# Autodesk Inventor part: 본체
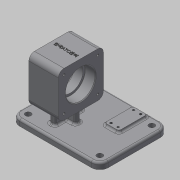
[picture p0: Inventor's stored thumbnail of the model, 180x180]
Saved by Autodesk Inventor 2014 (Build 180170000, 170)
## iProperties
Created: 2019-09
Part Number: 본체
Material: 일반
Document SubType Name: Modeling
Designer: mduedu
Density: 1 g/cm^3
Appearance: 기본값
Author: mduedu
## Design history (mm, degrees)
sketch "스케치1"
  geometry: L1 (42, -62)-(-84, -62); L2 (-84, -62)-(-84, 36); L3 (-84, 36)-(42, 36); L4 (42, 36)-(42, -62); 1 further point
  constraints: 8 end point, 2 parallel, 1 horizontal, 1 perpendicular
  dimensions: "d0" = 36 distance from line of L3 point (0, 0); "d1" = 98 distance of L1.end L2.end; "d2" = 42 distance from line of L4 point (0, 0); "d3" = 126 distance of L2.end L3.end
extrude "돌출1" new body sketch "스케치1" distance "d4" = 9; taper "d5" = 0 deg
sketch "스케치2"
  geometry: L1 (0, -62)-(0, 36) reference; L2 (27, -32)-(91, -32); L3 (91, -32)-(91, 32); L4 (91, 32)-(27, 32); L5 (27, 32)-(27, -32); L6 (27, -32)-(91, 32); L7 (91, -32)-(27, 32); 3 further points
  constraints: 12 end point, 3 midpoint, 2 parallel, 1 horizontal, 1 horizontal alignment, 1 perpendicular
  dimensions: "d87" = 64 distance of L4.end L3.end; "d88" = 64 distance of L3.end L2.end; "d89" = 59 distance from line of point (59, 0) L1
extrude "돌출2" join sketch "스케치2" stored distance "d8" = 42; taper "d9" = 0 deg
sketch "스케치3"
  geometry: L1 (-17, 4)-(17, 4); L2 (17, 4)-(17, -4); L3 (17, -4)-(-17, -4); L4 (-17, -4)-(-17, 4); L5 (-4, 20)-(4, 20); L6 (4, 20)-(4, -20); L7 (4, -20)-(-4, -20); L8 (-4, -20)-(-4, 20); 5 further points
  constraints: 16 end point, 4 midpoint, 4 parallel, 2 horizontal, 2 horizontal alignment, 2 perpendicular, 2 vertical alignment
  dimensions: "d10" = 8 distance of L5.start L5.end; "d12" = 8 distance of L1.end L2.end; "d13" = 34 distance of L2.end L3.end; "d14" = 40 distance of L5.end L6.end
extrude "돌출3" join sketch "스케치3" stored distance "d15" = 42; taper "d16" = 0 deg
sketch "스케치4"
  geometry: L1 (-32, 91)-(-32, 27) reference; L2 (32, 91)-(-32, 91) reference; L3 (32, 27)-(32, 91) reference; L4 (-32, 27)-(32, 27) reference; C1 r 21 at (0, 59); 3 further points
  constraints: 2 midpoint, 1 centre point, 1 horizontal alignment, 1 vertical alignment
  dimensions: "d17" = 42 diameter of C1
extrude "돌출4" cut sketch "스케치4" distance "d18" = 15; taper "d19" = 0 deg
hole "구멍1" diameter "d22" = 36; stored, may be unused: countersink angle "d26" = 90 deg, drill point angle "d28" = 118 deg; dims "d20" = 10, "d21" = 10, "d23" = 6, "d24" = 4, "d25" = 2, "d27" = 8
fillet "모깎기1" dims "d29" = 0.3
chamfer "모따기1" distance "d30" = 1; stored, may be unused: second distance "d31" = 2, angle "d32" = 45 deg
fillet "모깎기9" dims "d90" = 8
sketch "스케치11"
  geometry: L1 (-24, 27)-(24, 27) reference; L2 (32, 35)-(32, 83) reference; L3 (24, 91)-(-24, 91) reference; L4 (-32, 83)-(-32, 35) reference; C1 r 22 at (0, 59) reference; A1 r 8 centre (-24, 35) between (-32, 35) and (-24, 27) reference; A2 r 8 centre (24, 35) between (24, 27) and (32, 35) reference; A3 r 8 centre (24, 83) between (32, 83) and (24, 91) reference; A4 r 8 centre (-24, 83) between (-24, 91) and (-32, 83) reference; 5 further points
  constraints: 4 coincident
hole "구멍6" sketch "스케치11" at (-24, 83), (24, 83), (24, 35), (-24, 35) diameter "d91" = 3.242; stored, may be unused: countersink angle "d95" = 90 deg, drill point angle "d97" = 118 deg; dims "d92" = 8, "d93" = 4, "d94" = 2, "d96" = 10
fillet "모깎기2" dims "d44" = 12
sketch "스케치6"
  geometry: L1 (-42, 50)-(-42, -24) reference; L2 (-30, -36)-(72, -36) reference; L3 (84, -24)-(84, 50) reference; L4 (72, 62)-(-30, 62) reference; L5 (17, 4)-(17, -4) reference; L6 (17, -4)-(4, -4) reference; L7 (4, -4)-(4, -20) reference; L8 (4, -20)-(-4, -20) reference; L9 (-4, -20)-(-4, -4) reference; L10 (-4, -4)-(-17, -4) reference; L11 (-17, -4)-(-17, 4) reference; L12 (-17, 4)-(-4, 4) reference; L13 (-4, 4)-(-4, 20) reference; L14 (-4, 20)-(4, 20) reference; L15 (4, 20)-(4, 4) reference; L16 (4, 4)-(17, 4) reference; A1 r 12 centre (-30, 50) between (-30, 62) and (-42, 50) reference; A2 r 12 centre (-30, -24) between (-42, -24) and (-30, -36) reference; A3 r 12 centre (72, -24) between (72, -36) and (84, -24) reference; A4 r 12 centre (72, 50) between (84, 50) and (72, 62) reference; 5 further points
  constraints: 4 coincident
hole "구멍3" sketch "스케치6" at (-30, 50), (72, 50), (72, -24), (-30, -24) diameter "d45" = 8; stored, may be unused: countersink angle "d49" = 90 deg, drill point angle "d51" = 118 deg; dims "d46" = 8, "d47" = 4, "d48" = 2, "d50" = 10
sketch "스케치7"
  geometry: L1 (38, 57)-(58, 57); L2 (58, 57)-(58, 17); L3 (58, 17)-(38, 17); L4 (38, 17)-(38, 57); L5 (72, 62)-(-30, 62) reference; 3 further points
  constraints: 8 end point, 2 midpoint, 2 parallel, 1 horizontal, 1 perpendicular
  dimensions: "d52" = 48 horizontal distance of point (48, 57) point (0, 0); "d53" = 20 distance of L1.start L1.end; "d54" = 40 distance of L1.end L2.end; "d55" = 25 distance from line of point (38, 37) L5
extrude "돌출5" join sketch "스케치7" distance "d56" = 3; taper "d57" = 0 deg
fillet "모깎기3" dims "d58" = 3
fillet "모깎기4" dims "d59" = 3
fillet "모깎기5" dims "d60" = 3
fillet "모깎기6" dims "d61" = 3
fillet "모깎기7" dims "d62" = 3
fillet "모깎기8" dims "d63" = 3
sketch "스케치8"
  geometry: L1 (72, 62)-(58.317, 62) reference; L2 (84, -24)-(84, 50) reference; C1 r 1.5 at (43, 53); C2 r 1.5 at (53, 21); 1 further point
  constraints: 2 centre point, 1 equal radius
  dimensions: "d64" = 3 diameter of C1; "d65" = 9 distance from line of C1.centre L1; "d66" = 32 vertical distance of C2.centre C1.centre; "d67" = 10 horizontal distance of C2.centre C1.centre; "d68" = 31 distance from line of L2 C2.centre
hole "구멍4" sketch "스케치8" at (43, 53), (53, 21) diameter "d69" = 3; stored, may be unused: countersink angle "d73" = 90 deg, drill point angle "d75" = 118 deg; dims "d70" = 8, "d71" = 4, "d72" = 2, "d74" = 6
sketch "스케치9"
  geometry: C1 r 1.5 at (43, 53) reference; C2 r 1.5 at (53, 21) reference; 3 further points
  constraints: 2 horizontal alignment, 2 vertical alignment
hole "구멍5" sketch "스케치9" at (53, 53), (43, 21) diameter "d76" = 3.242; stored, may be unused: countersink angle "d80" = 90 deg, drill point angle "d82" = 118 deg; dims "d77" = 6, "d78" = 4, "d79" = 2, "d81" = 8
sketch "스케치10"
  geometry: 2 further points
  constraints: 1 coincident, 1 other
feature "엠보싱1" sketch "스케치10" dims "d0" = 36, "d1" = 98, "d2" = 42, "d3" = 126, "d12" = 8, "d13" = 34, "d85" = 0.5, "d86" = 0
node "솔리드1"
mirror "대칭1"
mirror "대칭2"
node "투영된 루프1"
node "투영된 루프2"
